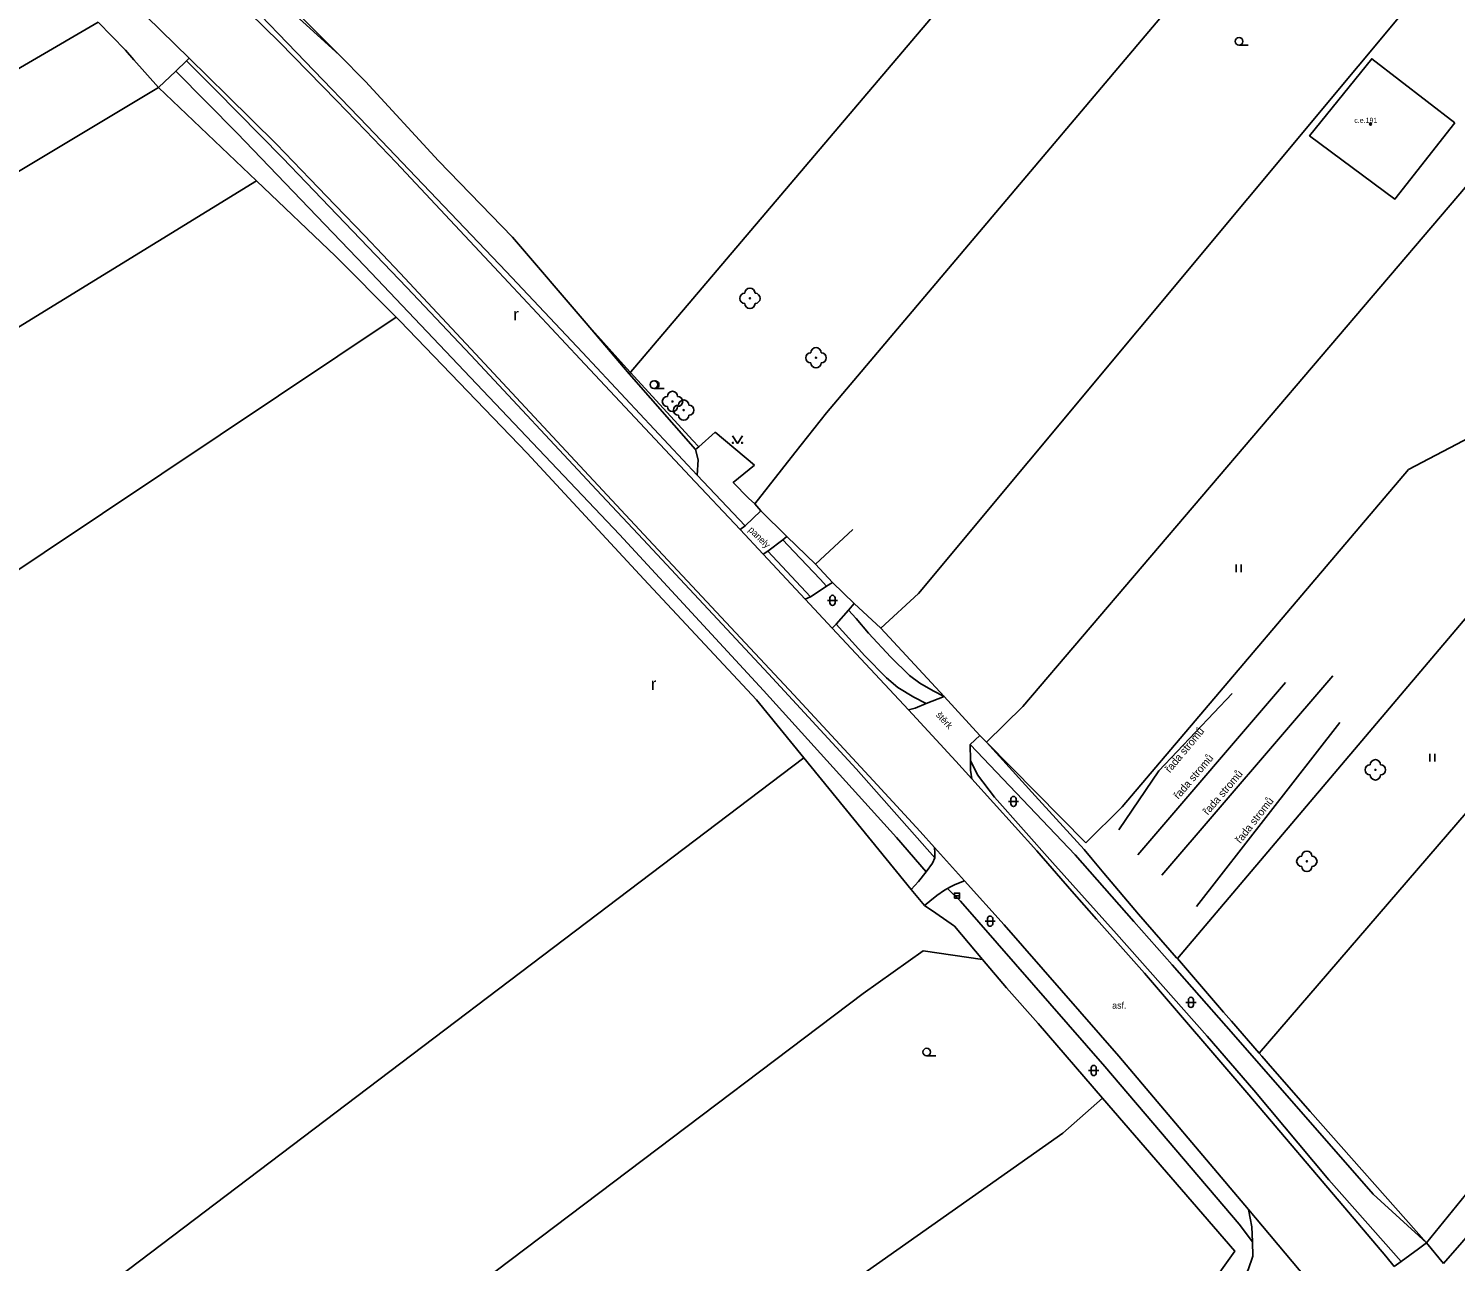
# Model space of a CAD drawing. Extents: x -594386 to -594050, y -1167541 to -1167175.
# Drawn here: x -594259.8 to -594119.8, y -1167451.4 to -1167330.4 of the extents above; entities that cross this region are included whole.
import ezdxf

# ---------------------------------------------------------------- set-up
doc = ezdxf.new("R2010")
doc.units = 0
for name, color, linetype in [('Level 14', 7, 'Continuous'), ('Level 22', 7, 'Continuous'), ('Level 27', 7, 'Continuous'), ('Level 36', 7, 'Continuous'), ('Level 39', 7, 'Continuous'), ('Level 41', 7, 'Continuous'), ('Vrstva 1', 7, 'Continuous'), ('Vrstva 10', 7, 'Continuous'), ('Vrstva 11', 7, 'Continuous'), ('Vrstva 40', 7, 'Continuous'), ('Vrstva 46', 7, 'Continuous'), ('Vrstva 51', 7, 'Continuous'), ('Vrstva 7', 7, 'Continuous'), ('Vrstva 8', 7, 'Continuous')]:
    doc.layers.add(name, color=color, linetype=linetype)

msp = doc.modelspace()

# ---------------------------------------------------------------- linework, layer by layer
at = {"layer": 'Level 14'}
for points in [[(-594239.66, -1167323.56), (-594229.34, -1167332.99)], [(-594229.34, -1167332.99), (-594226.75, -1167335.59), (-594219.58, -1167343.37), (-594212.34, -1167350.88), (-594205.12, -1167359.33)], [(-594205.12, -1167359.33), (-594200.89, -1167364.28)], [(-594200.89, -1167364.28), (-594194.38, -1167371.72)], [(-594194.21, -1167374.23), (-594194.11, -1167372.73), (-594194.38, -1167371.72)], [(-594185.82, -1167380.57), (-594184.73, -1167381.71), (-594182.15, -1167384.45), (-594181.52, -1167385.13)], [(-594170, -1167395.94), (-594171.06, -1167395.41), (-594172.37, -1167394.65), (-594173.4, -1167393.9), (-594175.22, -1167392.08), (-594177.41, -1167389.73), (-594178.63, -1167388.3), (-594179.38, -1167387.48)], [(-594169.65, -1167414.79), (-594168.39, -1167416.03), (-594154.24, -1167432.27), (-594141.06, -1167447.73), (-594139.75, -1167449.47)]]:
    msp.add_lwpolyline(points, dxfattribs=at)
at = {"layer": 'Level 22'}
for centre in [(-594189.04, -1167356.88), (-594182.56, -1167362.71), (-594196.64, -1167367), (-594195.54, -1167367.85), (-594127.69, -1167403.15), (-594134.41, -1167412.13)]:
    msp.add_circle(centre, 0.05, dxfattribs=at)
for centre, start, end in [((-594189.54, -1167356.88), 90, 270), ((-594189.04, -1167356.38), 0, 180), ((-594188.54, -1167356.88), 270, 90), ((-594189.04, -1167357.38), 180, 0), ((-594183.06, -1167362.71), 90, 270), ((-594182.56, -1167362.21), 0, 180), ((-594182.06, -1167362.71), 270, 90), ((-594182.56, -1167363.21), 180, 0), ((-594197.14, -1167367), 90, 270), ((-594196.64, -1167366.5), 0, 180), ((-594196.14, -1167367), 270, 90), ((-594196.64, -1167367.5), 180, 0), ((-594196.04, -1167367.85), 90, 270), ((-594195.54, -1167367.35), 0, 180), ((-594195.04, -1167367.85), 270, 90), ((-594195.54, -1167368.35), 180, 0), ((-594128.19, -1167403.15), 90, 270), ((-594127.69, -1167402.65), 0, 180), ((-594127.19, -1167403.15), 270, 90), ((-594127.69, -1167403.65), 180, 0), ((-594134.41, -1167411.63), 0, 180), ((-594134.91, -1167412.13), 90, 270), ((-594134.41, -1167412.63), 180, 0), ((-594133.91, -1167412.13), 270, 90)]:
    msp.add_arc(centre, 0.5, start, end, dxfattribs=at)
at = {"layer": 'Level 27'}
msp.add_line((-594168.98, -1167415.5), (-594168.48, -1167415.5), dxfattribs=at)
msp.add_lwpolyline([(-594168.98, -1167415.75), (-594168.48, -1167415.75), (-594168.48, -1167415.25), (-594168.98, -1167415.25)], close=True, dxfattribs=at)
at = {"layer": 'Level 36'}
for p, q in [((-594141.06, -1167332.03), (-594140.18, -1167332.03)), ((-594198.46, -1167365.73), (-594197.46, -1167365.73)), ((-594141.34, -1167383.74), (-594141.34, -1167382.99)), ((-594140.84, -1167383.74), (-594140.84, -1167382.99)), ((-594181.44, -1167386.52), (-594180.44, -1167386.52)), ((-594181.19, -1167386.27), (-594181.19, -1167386.77)), ((-594180.69, -1167386.27), (-594180.69, -1167386.77)), ((-594122.36, -1167402.32), (-594122.36, -1167401.57)), ((-594121.86, -1167402.32), (-594121.86, -1167401.57)), ((-594163.69, -1167406.25), (-594162.69, -1167406.25)), ((-594163.44, -1167406), (-594163.44, -1167406.5)), ((-594162.94, -1167406), (-594162.94, -1167406.5)), ((-594165.98, -1167418), (-594164.98, -1167418)), ((-594165.73, -1167417.75), (-594165.73, -1167418.25)), ((-594165.23, -1167417.75), (-594165.23, -1167418.25)), ((-594146.28, -1167425.97), (-594145.28, -1167425.97)), ((-594146.03, -1167425.72), (-594146.03, -1167426.22)), ((-594145.53, -1167425.72), (-594145.53, -1167426.22)), ((-594171.7, -1167431.23), (-594170.82, -1167431.23)), ((-594155.82, -1167432.65), (-594154.82, -1167432.65)), ((-594155.57, -1167432.4), (-594155.57, -1167432.9)), ((-594155.07, -1167432.4), (-594155.07, -1167432.9))]:
    msp.add_line(p, q, dxfattribs=at)
msp.add_lwpolyline([(-594190.76, -1167370.36), (-594190.26, -1167371.11), (-594189.76, -1167370.36)], dxfattribs=at)
for centre, radius in [((-594141.06, -1167331.66), 0.375), ((-594198.46, -1167365.35), 0.375), ((-594190.71, -1167371.06), 0.05), ((-594189.81, -1167371.06), 0.05), ((-594171.7, -1167430.85), 0.375)]:
    msp.add_circle(centre, radius, dxfattribs=at)
for centre, radius, start, end in [((-594198.34, -1167365.35), 0.375, 260.4059, 99.5941), ((-594180.94, -1167386.27), 0.25, 0, 180), ((-594180.94, -1167386.77), 0.25, 180, 0), ((-594163.19, -1167406), 0.25, 0, 180), ((-594163.19, -1167406.5), 0.25, 180, 0), ((-594165.48, -1167417.75), 0.25, 0, 180), ((-594165.48, -1167418.25), 0.25, 180, 0), ((-594145.78, -1167425.72), 0.25, 0, 180), ((-594145.78, -1167426.22), 0.25, 180, 0), ((-594155.32, -1167432.4), 0.25, 0, 180), ((-594155.32, -1167432.9), 0.25, 180, 0)]:
    msp.add_arc(centre, radius, start, end, dxfattribs=at)
at = {"layer": 'Level 39'}
for radius in [0.09, 0.0398]:
    msp.add_circle((-594128.16, -1167339.78), radius, dxfattribs=at)
at = {"layer": 'Vrstva 1'}
msp.add_lwpolyline([(-594194.07, -1167371.44), (-594194.67, -1167370.81), (-594200.77, -1167364.14), (-594201.16, -1167363.72), (-594205.12, -1167359.33)], dxfattribs=at)
at = {"layer": 'Vrstva 10'}
for points in [[(-594241.53, -1167325.54), (-594239.65, -1167327.35), (-594235.19, -1167331.75), (-594229.59, -1167337.47), (-594226.74, -1167340.41), (-594223.76, -1167343.56), (-594214.14, -1167353.82), (-594205.68, -1167362.85), (-594194.93, -1167374.34)], [(-594249.64, -1167327.86), (-594244.05, -1167333.32)], [(-594244.05, -1167333.32), (-594240.31, -1167336.98), (-594235.49, -1167341.76), (-594232.21, -1167345.16), (-594229.73, -1167347.73), (-594226.82, -1167350.76), (-594223.36, -1167354.41), (-594220.65, -1167357.31), (-594215.97, -1167362.34), (-594206.2, -1167372.83), (-594198.99, -1167380.55)], [(-594194.93, -1167374.34), (-594190, -1167379.57)], [(-594190, -1167379.57), (-594187.75, -1167381.98)], [(-594198.99, -1167380.55), (-594184.75, -1167395.78), (-594176.96, -1167404.18), (-594172.34, -1167409.2)], [(-594187.75, -1167381.98), (-594183.63, -1167386.4)], [(-594183.63, -1167386.4), (-594180.96, -1167389.25)], [(-594180.96, -1167389.25), (-594173.48, -1167397.26)], [(-594173.48, -1167397.26), (-594168.85, -1167402.31)], [(-594168.85, -1167402.31), (-594167.29, -1167404.04)], [(-594167.29, -1167404.04), (-594160.9, -1167411.1)], [(-594172.34, -1167409.2), (-594170.95, -1167410.78)], [(-594170.95, -1167410.78), (-594168.01, -1167414.05)], [(-594160.9, -1167411.1), (-594157.45, -1167415.05)], [(-594168.01, -1167414.05), (-594164.11, -1167418.37), (-594152.86, -1167431.24), (-594140.14, -1167446.31)], [(-594157.45, -1167415.05), (-594155.04, -1167417.79), (-594150.35, -1167423.11), (-594140.11, -1167435.03), (-594130.32, -1167446.56), (-594126.67, -1167450.89)], [(-594140.14, -1167446.31), (-594129.52, -1167458.94)], [(-594140.14, -1167446.31), (-594139.81, -1167448), (-594139.75, -1167449.47)], [(-594139.75, -1167449.47), (-594139.7, -1167450.87)], [(-594139.7, -1167450.87), (-594140.18, -1167452.21), (-594140.81, -1167453.25), (-594141.67, -1167454.31), (-594142.79, -1167455.28), (-594143.9, -1167456.06)], [(-594126.67, -1167450.89), (-594125.84, -1167451.9)]]:
    msp.add_lwpolyline(points, dxfattribs=at)
at = {"layer": 'Vrstva 11'}
for points in [[(-594229.34, -1167332.99), (-594235.08, -1167327.19), (-594236.4, -1167325.79), (-594239.03, -1167322.92)], [(-594241.06, -1167325.06), (-594238.77, -1167327.25), (-594226.55, -1167339.98), (-594212.97, -1167354.25), (-594205.48, -1167362.18), (-594194.21, -1167374.23)], [(-594245.37, -1167334.58), (-594244.3, -1167333.56)], [(-594244.3, -1167333.56), (-594244.05, -1167333.32)], [(-594199.53, -1167380.53), (-594204.1, -1167375.66), (-594216.42, -1167362.47), (-594222.69, -1167355.8), (-594232.57, -1167345.5), (-594234.9, -1167343.08), (-594241.43, -1167336.46), (-594244.3, -1167333.56)], [(-594119.9, -1167339.66), (-594125.77, -1167347.13), (-594134.14, -1167340.92), (-594128.04, -1167333.36), (-594119.9, -1167339.66)], [(-594247.06, -1167336.19), (-594245.37, -1167334.58)], [(-594171.77, -1167413.15), (-594174.66, -1167409.79), (-594187.71, -1167395.36), (-594201.84, -1167380.04), (-594226.83, -1167353.71), (-594239.35, -1167340.68), (-594245.37, -1167334.58)], [(-594247.06, -1167336.19), (-594237.45, -1167345.36)], [(-594237.45, -1167345.36), (-594229.7, -1167352.75), (-594223.76, -1167358.71)], [(-594124.45, -1167373.66), (-594092.14, -1167356.73)], [(-594223.76, -1167358.71), (-594223.4, -1167359.07), (-594210.91, -1167372.07), (-594199.45, -1167384.44), (-594188.4, -1167396.29), (-594183.77, -1167401.96)], [(-594194.07, -1167371.44), (-594192.46, -1167370.01)], [(-594192.46, -1167370.01), (-594188.6, -1167373.24)], [(-594194.38, -1167371.72), (-594194.07, -1167371.44)], [(-594188.6, -1167373.24), (-594190.68, -1167374.95), (-594189.17, -1167376.5), (-594188.56, -1167377.06)], [(-594194.21, -1167374.23), (-594189.51, -1167379.19)], [(-594187.97, -1167377.72), (-594189.51, -1167379.19)], [(-594170.91, -1167411.79), (-594178.62, -1167403.04), (-594187.22, -1167393.73), (-594199.53, -1167380.53)], [(-594189.51, -1167379.19), (-594190, -1167379.57)], [(-594185.41, -1167380.26), (-594185.82, -1167380.57)], [(-594187.29, -1167381.69), (-594187.75, -1167381.98)], [(-594185.82, -1167380.57), (-594187.29, -1167381.69)], [(-594183.1, -1167386.16), (-594187.29, -1167381.69)], [(-594183.1, -1167386.16), (-594182.15, -1167385.54), (-594181.52, -1167385.13)], [(-594181.52, -1167385.13), (-594180.93, -1167384.76)], [(-594183.63, -1167386.4), (-594183.1, -1167386.16)], [(-594180.59, -1167388.84), (-594179.38, -1167387.48)], [(-594179.38, -1167387.48), (-594178.81, -1167386.84)], [(-594180.96, -1167389.25), (-594180.59, -1167388.84)], [(-594180.59, -1167388.84), (-594177.77, -1167391.96), (-594175.63, -1167394.11), (-594174.53, -1167395.06), (-594172.97, -1167396.02), (-594171.76, -1167396.65)], [(-594170, -1167395.94), (-594171.76, -1167396.65)], [(-594121, -1167451.58), (-594079.89, -1167404.5), (-594071.72, -1167395.67)], [(-594171.76, -1167396.65), (-594172.82, -1167397.09), (-594173.48, -1167397.26)], [(-594166.48, -1167399.77), (-594167.43, -1167400.66)], [(-594167.43, -1167400.66), (-594157.15, -1167411.48)], [(-594167.43, -1167400.66), (-594167.41, -1167402.24)], [(-594150.92, -1167417.3), (-594154.31, -1167413.29), (-594155.46, -1167411.92), (-594156.26, -1167410.97), (-594161.06, -1167405.71), (-594165.85, -1167400.42)], [(-594156.1, -1167410.3), (-594165.85, -1167400.42)], [(-594183.77, -1167401.96), (-594173.22, -1167414.88)], [(-594167.41, -1167402.24), (-594167.4, -1167403.19), (-594167.29, -1167404.04)], [(-594159.35, -1167412.25), (-594165.05, -1167405.84), (-594166.73, -1167403.64), (-594167.41, -1167402.24)], [(-594115.73, -1167403.84), (-594139.08, -1167430.97)], [(-594156.1, -1167410.3), (-594152.54, -1167406.79)], [(-594170.91, -1167411.79), (-594170.91, -1167411.29), (-594170.95, -1167410.78)], [(-594171.77, -1167413.15), (-594171.14, -1167412.3), (-594170.91, -1167411.79)], [(-594144.18, -1167429.3), (-594153.08, -1167419.23), (-594159.35, -1167412.25)], [(-594157.15, -1167411.48), (-594151.39, -1167418.02)], [(-594173.22, -1167414.88), (-594172.52, -1167414.12), (-594171.77, -1167413.15)], [(-594168.01, -1167414.05), (-594168.91, -1167414.39)], [(-594171.92, -1167416.45), (-594173.22, -1167414.88)], [(-594169.65, -1167414.79), (-594169.94, -1167414.95), (-594170.7, -1167415.48), (-594171.41, -1167416.04), (-594171.92, -1167416.45)], [(-594168.91, -1167414.39), (-594169.37, -1167414.63), (-594169.65, -1167414.79)], [(-594171.92, -1167416.45), (-594170.81, -1167417.21), (-594168.99, -1167418.49)], [(-594151.39, -1167418.02), (-594147.63, -1167422.29)], [(-594147.11, -1167421.67), (-594147.19, -1167421.6), (-594150.92, -1167417.3)], [(-594147.63, -1167422.29), (-594142.32, -1167428.32)], [(-594141.8, -1167427.83), (-594142.58, -1167426.93), (-594147.11, -1167421.67)], [(-594139.08, -1167430.97), (-594141.8, -1167427.83)], [(-594125.15, -1167451.39), (-594128.69, -1167447.42), (-594132.27, -1167443.38), (-594139.6, -1167434.58), (-594144.18, -1167429.3)], [(-594142.32, -1167428.32), (-594139.53, -1167431.49)], [(-594139.53, -1167431.49), (-594127.89, -1167444.78), (-594122.67, -1167449.58)], [(-594122.67, -1167449.58), (-594134.09, -1167436.67), (-594137.78, -1167432.45), (-594138.84, -1167431.25), (-594139.08, -1167430.97)], [(-594123.47, -1167450.16), (-594125.15, -1167451.39)], [(-594122.67, -1167449.58), (-594123.47, -1167450.16)], [(-594125.15, -1167451.39), (-594125.84, -1167451.9)]]:
    msp.add_lwpolyline(points, dxfattribs=at)
at = {"layer": 'Vrstva 51'}
for points in [[(-594102.27, -1167248.02), (-594200.89, -1167364.28)], [(-594181.54, -1167368.12), (-594089, -1167258.56)], [(-594172.52, -1167385.86), (-594075.44, -1167269.34)], [(-594068.61, -1167287), (-594162.26, -1167396.94)], [(-594363.06, -1167394.04), (-594252.98, -1167329.77)], [(-594336.26, -1167389.69), (-594247.06, -1167336.19)], [(-594362.44, -1167422.23), (-594237.45, -1167345.36)], [(-594092.14, -1167356.73), (-594147.11, -1167421.67)], [(-594223.76, -1167358.71), (-594350.36, -1167443.4)], [(-594124.45, -1167373.66), (-594152.54, -1167406.79)], [(-594183.77, -1167401.96), (-594314.13, -1167500.77)], [(-594177.93, -1167425.11), (-594300.42, -1167517.66)], [(-594158.36, -1167438.82), (-594185.49, -1167457.95)]]:
    msp.add_lwpolyline(points, dxfattribs=at)
at = {"layer": 'Vrstva 7'}
for points in [[(-594184.63, -1167372.05), (-594181.54, -1167368.12)], [(-594188.56, -1167377.06), (-594184.63, -1167372.05)], [(-594187.97, -1167377.72), (-594188.56, -1167377.06)], [(-594182.61, -1167382.95), (-594185.41, -1167380.26)], [(-594182.61, -1167382.95), (-594178.94, -1167379.55)], [(-594180.93, -1167384.76), (-594182.61, -1167382.95)], [(-594176.19, -1167389.26), (-594172.52, -1167385.86)], [(-594176.19, -1167389.26), (-594178.81, -1167386.84)], [(-594170, -1167395.94), (-594176.19, -1167389.26)], [(-594131.87, -1167393.93), (-594148.62, -1167413.5)], [(-594152.86, -1167409.05), (-594148.94, -1167403.24), (-594141.74, -1167395.67)], [(-594150.98, -1167411.48), (-594136.51, -1167394.57)], [(-594165.85, -1167400.42), (-594162.26, -1167396.94)], [(-594145.22, -1167416.56), (-594131.16, -1167398.5)], [(-594165.85, -1167400.42), (-594166.48, -1167399.77)], [(-594166.22, -1167421.76), (-594168.99, -1167418.49)], [(-594177.93, -1167425.11), (-594172.05, -1167420.91), (-594166.22, -1167421.76)], [(-594163.87, -1167424.53), (-594166.22, -1167421.76)], [(-594163.87, -1167424.53), (-594160.78, -1167428.03), (-594154.47, -1167435.37)], [(-594158.36, -1167438.82), (-594154.47, -1167435.37)], [(-594154.47, -1167435.37), (-594141.48, -1167450.37), (-594144.81, -1167455.06)], [(-594112.89, -1167437.53), (-594122.67, -1167449.58)]]:
    msp.add_lwpolyline(points, dxfattribs=at)
at = {"layer": 'Vrstva 8'}
for points in [[(-594252.98, -1167329.77), (-594250.3, -1167332.52)], [(-594249.47, -1167333.48), (-594250.3, -1167332.52)], [(-594249.47, -1167333.48), (-594247.06, -1167336.19)], [(-594187.97, -1167377.72), (-594185.41, -1167380.26)], [(-594180.93, -1167384.76), (-594178.81, -1167386.84)], [(-594170, -1167395.94), (-594166.48, -1167399.77)], [(-594121, -1167451.58), (-594122.67, -1167449.58)]]:
    msp.add_lwpolyline(points, dxfattribs=at)

# ---------------------------------------------------------------- texts
at = {"layer": 'Level 36'}
for p in [(-594212.25, -1167359.05), (-594198.75, -1167395.31)]:
    msp.add_text('r', height=1.2, dxfattribs=at).set_placement(p)
at = {"layer": 'Level 41'}
for rotation, p in [(50.2703, (-594147.84, -1167403.49)), (49.4462, (-594147, -1167406.09)), (49.4397, (-594144.12, -1167407.64)), (52.0987, (-594140.91, -1167410.43))]:
    msp.add_text('řada stromů', height=0.75, rotation=rotation, dxfattribs=at).set_placement(p)
at = {"layer": 'Vrstva 40'}
for s, rotation, p in [('panely', 315.22, (-594189.25, -1167379.65)), ('štěrk', 312.58, (-594170.84, -1167397.81))]:
    msp.add_text(s, height=0.65, rotation=rotation, dxfattribs=at).set_placement(p)
msp.add_text('asf.', height=0.65, dxfattribs=at).set_placement((-594153.51, -1167426.59))
at = {"layer": 'Vrstva 46'}
msp.add_text('c.e.191', height=0.5, dxfattribs=at).set_placement((-594129.76, -1167339.66))

doc.saveas('drawing.dxf')
